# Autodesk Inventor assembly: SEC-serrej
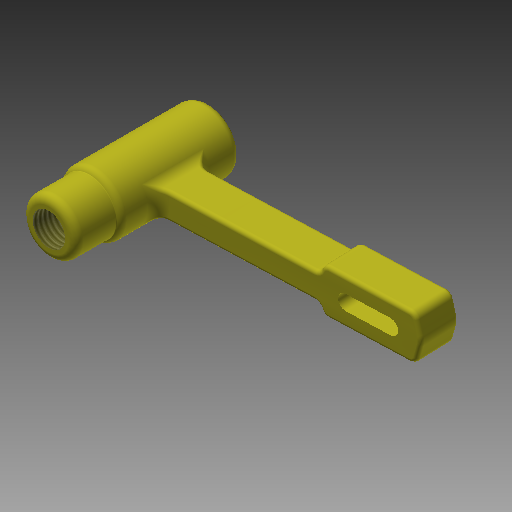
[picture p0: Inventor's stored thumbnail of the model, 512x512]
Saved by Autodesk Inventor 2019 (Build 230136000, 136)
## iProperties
Created: 2019-02
Part Number: SEC-serrej
Material: Générique
Document SubType Name: Assembly
Designer: si-nd67
Mass: 77.4638 g
Surface Area: 267.638 cm^2
Volume: 77.4638 cm^3
Density: 1 g/cm^3
Author: si-nd67
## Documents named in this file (3)
- E:\ECAM\serrejointsw\SEC-serrej.iam
- E:\ECAM\serrejointsw\Mors mobile14.ipt
- E:\ECAM\serrejointsw\GoupilleElast112-14.ipt
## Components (2 placed, 2 different names)
1. Mors mobile14:1 — Placage:1, Placage:2
2. GoupilleElast112-14:1 — Placage:1, Placage:2
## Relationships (2: Mate 2)
- Placage:1 [Mate]: Mors mobile14:1 ↔ GoupilleElast112-14:1
- Placage:2 [Mate]: Mors mobile14:1 ↔ GoupilleElast112-14:1
